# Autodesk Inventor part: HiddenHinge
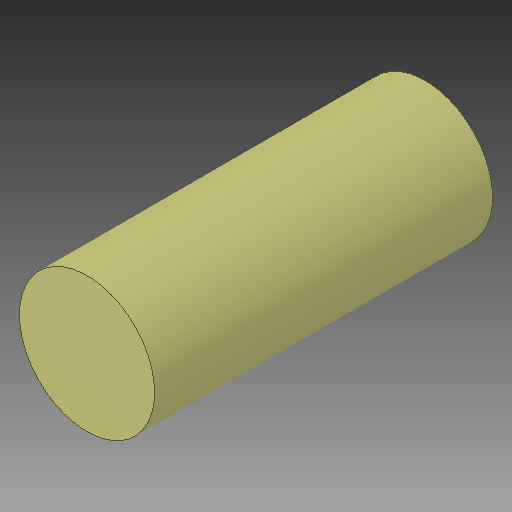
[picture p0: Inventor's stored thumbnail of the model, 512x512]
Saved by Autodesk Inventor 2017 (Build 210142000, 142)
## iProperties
Created: 2017-05
Part Number: HiddenHinge
Material: Generic
Document SubType Name: Modeling
Designer: Savy
Density: 1 g/cm^3
Appearance: Default
Author: Savy
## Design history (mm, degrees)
feature "Base1"
body "Solid1"
